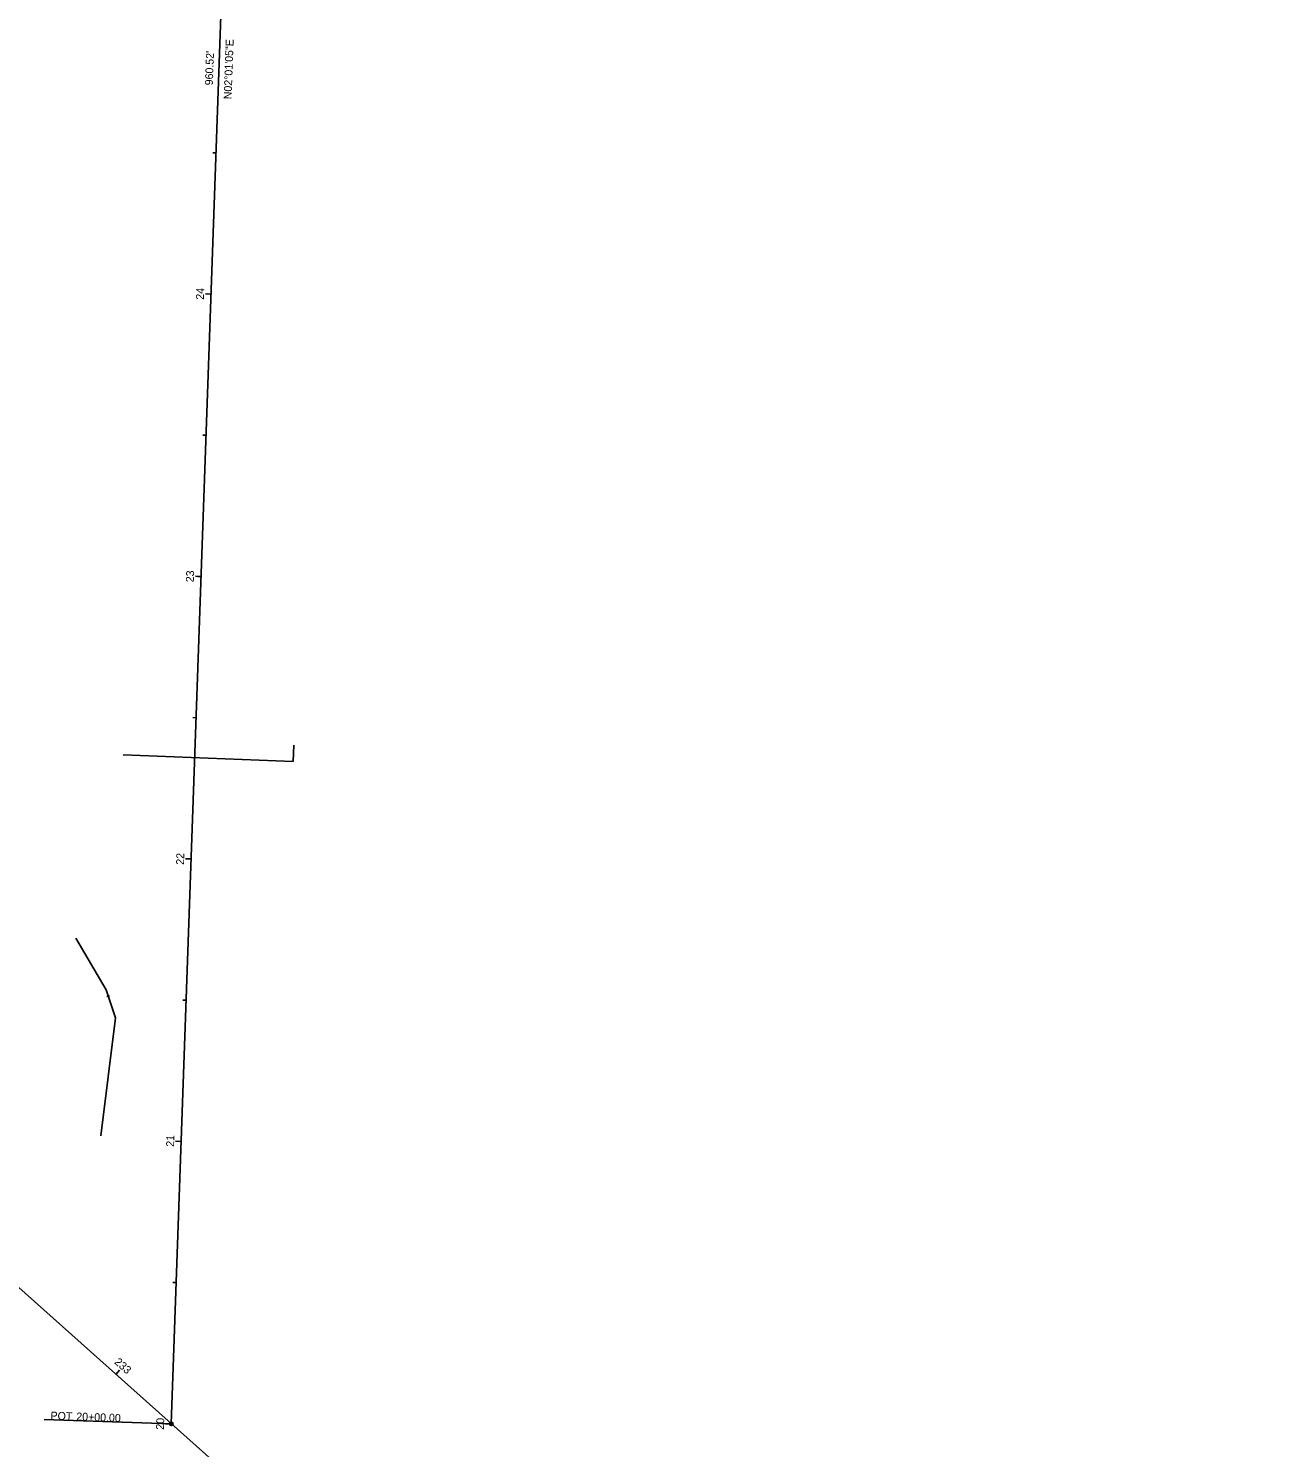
# Model space of a CAD drawing. Extents: x 1471653 to 1473622, y 385397 to 387214.
# Drawn here: x 1472593 to 1473039, y 386241 to 386744 of the extents above; entities that cross this region are included whole.
import ezdxf

# ---------------------------------------------------------------- set-up
doc = ezdxf.new("R2010")
doc.units = 0
for name, color, linetype in [('CM_Corridor_Final', 7, 'Continuous'), ('Default', 7, 'Continuous'), ('DT_P_Graded_Shoulder', 7, 'Continuous'), ('GE_X_Alignment', 7, 'Continuous'), ('MD_P_ACSC_B', 7, 'Continuous'), ('PV_P_Curb', 7, 'Continuous'), ('PV_P_EOP', 7, 'Continuous')]:
    doc.layers.add(name, color=color, linetype=linetype)

msp = doc.modelspace()

# ---------------------------------------------------------------- linework, layer by layer
at = {"layer": 'CM_Corridor_Final'}
msp.add_line((1472620.97, 386400.99), (1472621.92, 386401.31), dxfattribs=at)
at = {"layer": 'Default'}
for centre in [(1472660.69, 386729.78), (1472660.69, 386729.78), (1472660.69, 386729.78), (1472660.69, 386729.78), (1472660.69, 386729.78), (1472660.69, 386729.78), (1472657.87, 386649.57), (1472654.34, 386549.64), (1472650.82, 386449.7), (1472647.3, 386349.76), (1472624.17, 386267.32), (1472643.78, 386249.82), (1472643.78, 386249.82), (1472643.78, 386249.82), (1472643.78, 386249.82), (1472643.78, 386249.82), (1472643.78, 386249.82)]:
    msp.add_circle(centre, 0.0000833, dxfattribs=at)
at = {"layer": 'DT_P_Graded_Shoulder'}
for p, q in [((1472657.87, 386649.57), (1472656.67, 386649.62)), ((1472654.34, 386549.64), (1472653.14, 386549.68)), ((1472650.82, 386449.7), (1472649.62, 386449.74)), ((1472647.3, 386349.76), (1472646.1, 386349.8)), ((1472624.17, 386267.32), (1472624.97, 386268.21)), ((1472643.78, 386249.82), (1472598.81, 386251.41)), ((1472643.78, 386249.82), (1472641.78, 386249.89))]:
    msp.add_line(p, q, dxfattribs=at)
msp.add_circle((1472643.78, 386249.82), 0.6, dxfattribs=at)
at = {"layer": 'GE_X_Alignment'}
for q in [(1472598.81, 386251.41), (1472641.78, 386249.89)]:
    msp.add_line((1472643.78, 386249.82), q, dxfattribs=at)
msp.add_circle((1472643.78, 386249.82), 0.6, dxfattribs=at)
at = {"layer": 'MD_P_ACSC_B'}
for p, q in [((1472626.8, 386486.55), (1472686.88, 386484.18)), ((1472686.88, 386484.18), (1472687.16, 386489.98)), ((1472610.03, 386421.71), (1472620.69, 386403.34)), ((1472620.69, 386403.34), (1472624.07, 386393.43)), ((1472624.07, 386393.43), (1472618.91, 386351.74))]:
    msp.add_line(p, q, dxfattribs=at)
at = {"layer": 'PV_P_Curb'}
for p, q in [((1472643.78, 386249.82), (1472677.6, 387209.74)), ((1471654.09, 387132.73), (1473038.58, 385897.62))]:
    msp.add_line(p, q, dxfattribs=at)
at = {"layer": 'PV_P_EOP'}
for p, q in [((1472659.63, 386699.54), (1472658.43, 386699.58)), ((1472657.87, 386649.57), (1472655.87, 386649.64)), ((1472656.1, 386599.6), (1472654.91, 386599.65)), ((1472654.34, 386549.64), (1472652.35, 386549.71)), ((1472652.58, 386499.67), (1472651.38, 386499.71)), ((1472650.82, 386449.7), (1472648.82, 386449.77)), ((1472649.06, 386399.73), (1472647.86, 386399.77)), ((1472647.3, 386349.76), (1472645.3, 386349.83)), ((1472645.54, 386299.79), (1472644.34, 386299.83)), ((1472624.17, 386267.32), (1472625.5, 386268.81)), ((1472643.78, 386249.82), (1472598.81, 386251.41)), ((1472643.78, 386249.82), (1472641.78, 386249.89))]:
    msp.add_line(p, q, dxfattribs=at)
msp.add_circle((1472643.78, 386249.82), 0.6, dxfattribs=at)

# ---------------------------------------------------------------- texts
at = {"layer": 'DT_P_Graded_Shoulder'}
for s, rotation, p in [('N02°01\'05"E', 87.982, (1472665.09, 386718.44)), ("960.52'", 87.982, (1472658.46, 386723.37)), ('POT', 357.982, (1472601.02, 386251.37)), ('20+00.00', 357.982, (1472610.14, 386251.05)), ('20', 87.982, (1472641.16, 386247.72))]:
    msp.add_text(s, height=2.8, rotation=rotation, dxfattribs=at).set_placement(p)
at = {"layer": 'GE_X_Alignment'}
for s, rotation, p in [('N02°01\'05"E', 87.982, (1472665.09, 386718.44)), ("960.52'", 87.982, (1472658.46, 386723.37)), ('POT', 357.982, (1472601.02, 386251.37)), ('20+00.00', 357.982, (1472610.14, 386251.05)), ('20', 87.982, (1472641.16, 386247.72))]:
    msp.add_text(s, height=2.8, rotation=rotation, dxfattribs=at).set_placement(p)
at = {"layer": 'PV_P_EOP'}
for s, rotation, p in [('N02°01\'05"E', 87.982, (1472665.09, 386718.44)), ("960.52'", 87.982, (1472658.46, 386723.37)), ('24', 87.982, (1472655.29, 386647.51)), ('23', 87.982, (1472651.72, 386547.55)), ('22', 87.982, (1472648.25, 386447.6)), ('21', 87.982, (1472644.73, 386347.82)), ('233', 318.2637, (1472623.43, 386271.39)), ('POT', 357.982, (1472601.02, 386251.37)), ('20+00.00', 357.982, (1472610.14, 386251.05)), ('20', 87.982, (1472641.16, 386247.72))]:
    msp.add_text(s, height=2.8, rotation=rotation, dxfattribs=at).set_placement(p)

doc.saveas('drawing.dxf')
